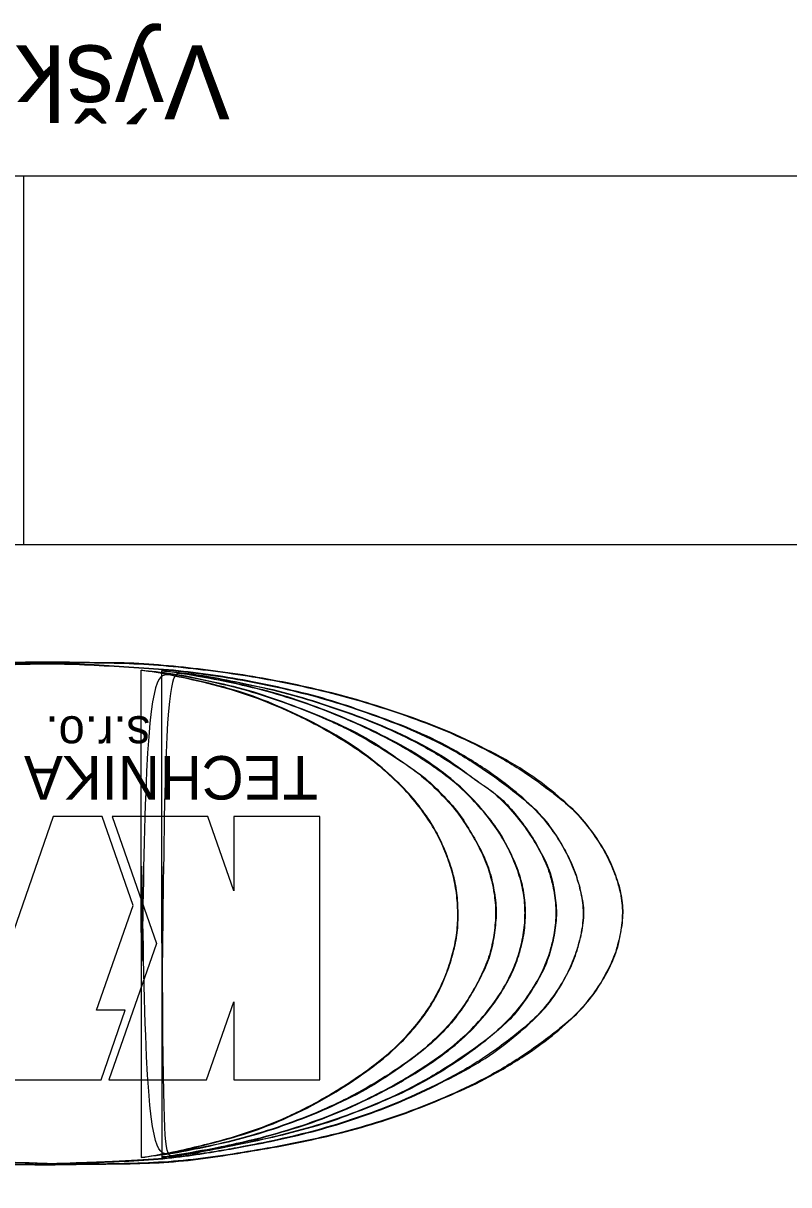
# Model space of a CAD drawing. Extents: x -728472.2 to -728419.7, y -1073099.3 to -1073025.
# Drawn here: x -728457.28 to -728452.08, y -1073054.87 to -1073046.99 of the extents above; entities that cross this region are included whole.
import ezdxf

# ---------------------------------------------------------------- set-up
doc = ezdxf.new("R2010")
doc.units = 0
doc.layers.add('_popis', color=7, linetype='Continuous')
doc.layers.add('Rozpiska_pole_6', color=7, linetype='Continuous')

msp = doc.modelspace()

# ---------------------------------------------------------------- linework, layer by layer
at = {"layer": '_popis'}
for points in [[(-728456.7476, -1073054.1561), (-728456.5834, -1073053.6842), (-728456.7772, -1073053.6842), (-728456.5302, -1073052.9747), (-728456.7404, -1073052.3709), (-728457.0726, -1073052.3709), (-728457.5297, -1073053.6842), (-728457.6809, -1073053.6842), (-728457.8451, -1073054.1561), (-728456.7476, -1073054.1561)], [(-728456.7476, -1073054.1561), (-728456.5834, -1073053.6842), (-728456.7772, -1073053.6842), (-728456.5302, -1073052.9747), (-728456.7404, -1073052.3709), (-728457.0726, -1073052.3709), (-728457.5297, -1073053.6842), (-728457.6809, -1073053.6842), (-728457.8451, -1073054.1561), (-728456.7476, -1073054.1561)], [(-728455.2632, -1073054.1561), (-728455.2632, -1073052.3709), (-728455.8474, -1073052.3709), (-728455.8474, -1073052.874), (-728456.0225, -1073052.3709), (-728456.6724, -1073052.3709), (-728456.3725, -1073053.2324), (-728456.694, -1073054.1561), (-728456.0316, -1073054.1561), (-728455.8474, -1073053.6268), (-728455.8474, -1073054.1561), (-728455.2632, -1073054.1561)], [(-728455.2632, -1073054.1561), (-728455.2632, -1073052.3709), (-728455.8474, -1073052.3709), (-728455.8474, -1073052.874), (-728456.0225, -1073052.3709), (-728456.6724, -1073052.3709), (-728456.3725, -1073053.2324), (-728456.694, -1073054.1561), (-728456.0316, -1073054.1561), (-728455.8474, -1073053.6268), (-728455.8474, -1073054.1561), (-728455.2632, -1073054.1561)]]:
    msp.add_lwpolyline(points, dxfattribs=at)
for points in [[(-728457.7091, -1073051.3386), (-728457.7726, -1073051.3422), (-728457.925, -1073051.3531), (-728458.1678, -1073051.3735), (-728458.4349, -1073051.4173), (-728458.7039, -1073051.4628), (-728458.9726, -1073051.5237), (-728459.2412, -1073051.5978), (-728459.5099, -1073051.6866), (-728459.779, -1073051.7895), (-728460.0492, -1073051.9158), (-728460.3251, -1073052.0723), (-728460.5215, -1073052.2333), (-728460.6799, -1073052.366), (-728460.7644, -1073052.4858), (-728460.8578, -1073052.6154), (-728460.9179, -1073052.7534), (-728460.9631, -1073052.8875), (-728460.989, -1073053.0235), (-728460.9707, -1073053.1621), (-728460.9194, -1073053.2951), (-728460.8626, -1073053.4322), (-728460.7785, -1073053.5688), (-728460.681, -1073053.6813), (-728460.5301, -1073053.8296), (-728460.3243, -1073053.9851), (-728460.0511, -1073054.1448), (-728459.7818, -1073054.2742), (-728459.5101, -1073054.3742), (-728459.2438, -1073054.4708), (-728458.9726, -1073054.5378), (-728458.7045, -1073054.6), (-728458.434, -1073054.6453), (-728458.1654, -1073054.6802), (-728457.8989, -1073054.7218), (-728457.6308, -1073054.7247), (-728457.363, -1073054.7305), (-728457.1843, -1073054.7318), (-728457.0948, -1073054.7325)], [(-728457.0948, -1073054.7325), (-728456.7918, -1073054.7282), (-728456.5586, -1073054.7252), (-728456.2906, -1073054.7141), (-728456.0227, -1073054.6861), (-728455.7547, -1073054.644), (-728455.4862, -1073054.5975), (-728455.2182, -1073054.54), (-728454.9503, -1073054.4699), (-728454.6816, -1073054.3822), (-728454.4137, -1073054.2757), (-728454.1472, -1073054.1523), (-728453.8786, -1073053.9935), (-728453.6107, -1073053.7917), (-728453.5065, -1073053.6944), (-728453.3971, -1073053.5598), (-728453.3157, -1073053.4266), (-728453.2554, -1073053.292), (-728453.2231, -1073053.1586), (-728453.2078, -1073053.0243), (-728453.2217, -1073052.8922), (-728453.2624, -1073052.7568), (-728453.3227, -1073052.6222), (-728453.4069, -1073052.489), (-728453.5149, -1073052.3544), (-728453.6106, -1073052.265), (-728453.8785, -1073052.0617), (-728454.1464, -1073051.9103), (-728454.4116, -1073051.787), (-728454.6823, -1073051.6846), (-728454.9512, -1073051.5973), (-728455.2178, -1073051.5244), (-728455.4843, -1073051.4655), (-728455.7536, -1073051.4164), (-728456.0224, -1073051.3784), (-728456.2917, -1073051.349), (-728456.5568, -1073051.3307), (-728456.8269, -1073051.3278), (-728457.0948, -1073051.3234), (-728457.3627, -1073051.3278), (-728457.6315, -1073051.3348), (-728457.8994, -1073051.3516), (-728458.166, -1073051.3768), (-728458.4347, -1073051.4175), (-728458.7027, -1073051.4652), (-728458.9706, -1073051.5254), (-728459.2396, -1073051.5998), (-728459.5075, -1073051.6881), (-728459.7754, -1073051.7918), (-728460.042, -1073051.9166), (-728460.312, -1073052.0746), (-728460.5813, -1073052.2835), (-728460.6613, -1073052.355), (-728460.7665, -1073052.4882), (-728460.8549, -1073052.6214), (-728460.917, -1073052.7567), (-728460.9605, -1073052.8899), (-728460.9818, -1073053.0243), (-728460.9661, -1073053.158), (-728460.9198, -1073053.2926), (-728460.8594, -1073053.4295), (-728460.7795, -1073053.5599), (-728460.6659, -1073053.6944), (-728460.5831, -1073053.7758), (-728460.3122, -1073053.9854), (-728460.0443, -1073054.1438), (-728459.7781, -1073054.2707), (-728459.5088, -1073054.3745), (-728459.2395, -1073054.467), (-728458.9729, -1073054.5371), (-728458.7028, -1073054.5974), (-728458.4334, -1073054.6437), (-728458.1641, -1073054.6816), (-728457.8983, -1073054.7154), (-728457.6309, -1073054.7252), (-728457.3633, -1073054.7299), (-728457.0948, -1073054.7325), (-728457.0948, -1073054.7325), (-728457.0948, -1073054.7325)], [(-728457.0948, -1073054.7252), (-728457.1843, -1073054.7215), (-728457.3632, -1073054.7142), (-728457.6318, -1073054.7117), (-728457.8994, -1073054.6823), (-728458.1675, -1073054.6482), (-728458.4362, -1073054.6035), (-728458.704, -1073054.5443), (-728458.9744, -1073054.4802), (-728459.2417, -1073054.389), (-728459.5122, -1073054.2858), (-728459.7795, -1073054.1537), (-728460.0582, -1073054.0039), (-728460.2639, -1073053.84), (-728460.4163, -1073053.6872), (-728460.5124, -1073053.566), (-728460.5949, -1073053.4304), (-728460.6561, -1073053.296), (-728460.6882, -1073053.1591), (-728460.6999, -1073053.0238), (-728460.6897, -1073052.8873), (-728460.6489, -1073052.7527), (-728460.5887, -1073052.6175), (-728460.5032, -1073052.4835), (-728460.4121, -1073052.3643), (-728460.2577, -1073052.2194), (-728460.0581, -1073052.0546), (-728459.7814, -1073051.8986), (-728459.511, -1073051.7735), (-728459.242, -1073051.669), (-728458.9724, -1073051.5847), (-728458.7045, -1073051.51), (-728458.4353, -1073051.4543), (-728458.1674, -1073051.4053), (-728457.8986, -1073051.379), (-728457.6309, -1073051.356), (-728457.3632, -1073051.3388), (-728457.0947, -1073051.3301), (-728456.8264, -1073051.3401), (-728456.5586, -1073051.3592), (-728456.2898, -1073051.3739), (-728456.0214, -1073051.4058), (-728455.7529, -1073051.4493), (-728455.4847, -1073051.5062), (-728455.2148, -1073051.5726), (-728454.9483, -1073051.6648), (-728454.6772, -1073051.7619), (-728454.4059, -1073051.8851), (-728454.1363, -1073052.0484), (-728453.9248, -1073052.2091), (-728453.7633, -1073052.3565), (-728453.6669, -1073052.4825), (-728453.5871, -1073052.6187), (-728453.5268, -1073052.7533), (-728453.4896, -1073052.8885), (-728453.4658, -1073053.0241), (-728453.4866, -1073053.1601), (-728453.5212, -1073053.2956), (-728453.578, -1073053.4308), (-728453.6574, -1073053.5657), (-728453.754, -1073053.6974), (-728453.9216, -1073053.8464), (-728454.1329, -1073054.0145), (-728454.4102, -1073054.1627), (-728454.6774, -1073054.2922), (-728454.947, -1073054.3972), (-728455.2159, -1073054.4831), (-728455.4849, -1073054.5519), (-728455.714, -1073054.5973), (-728455.8931, -1073054.6301), (-728456.0715, -1073054.6588), (-728456.2898, -1073054.6909), (-728456.5585, -1073054.7078), (-728456.8266, -1073054.7189), (-728457.0054, -1073054.7231), (-728457.0948, -1073054.7252)], [(-728457.0948, -1073054.7252), (-728456.8266, -1073054.7181), (-728456.5587, -1073054.7069), (-728456.2908, -1073054.6872), (-728456.0228, -1073054.6508), (-728455.9022, -1073054.6312), (-728455.7549, -1073054.6045), (-728455.4863, -1073054.5496), (-728455.2183, -1073054.4809), (-728454.9498, -1073054.3951), (-728454.6819, -1073054.2899), (-728454.4136, -1073054.1622), (-728454.1471, -1073054.0122), (-728453.8788, -1073053.8071), (-728453.7594, -1073053.6946), (-728453.657, -1073053.5601), (-728453.5798, -1073053.4269), (-728453.5237, -1073053.2919), (-728453.4886, -1073053.1587), (-728453.4732, -1073053.0241), (-728453.4914, -1073052.8903), (-728453.5293, -1073052.7571), (-728453.5882, -1073052.6225), (-728453.6669, -1073052.4885), (-728453.7721, -1073052.3539), (-728453.8787, -1073052.253), (-728454.1467, -1073052.0483), (-728454.4136, -1073051.8879), (-728454.6815, -1073051.7645), (-728454.9494, -1073051.665), (-728455.218, -1073051.5761), (-728455.4859, -1073051.5074), (-728455.7539, -1073051.4514), (-728456.0225, -1073051.4076), (-728456.2904, -1073051.3767), (-728456.5584, -1073051.3585), (-728456.8268, -1073051.3416), (-728457.0948, -1073051.3332), (-728457.3627, -1073051.3402), (-728457.6314, -1073051.357), (-728457.8979, -1073051.3795), (-728458.1659, -1073051.4089), (-728458.4346, -1073051.4553), (-728458.7025, -1073051.5127), (-728458.9705, -1073051.5856), (-728459.2393, -1073051.6715), (-728459.5073, -1073051.7752), (-728459.7752, -1073051.9), (-728460.0437, -1073052.0565), (-728460.3117, -1073052.271), (-728460.3975, -1073052.3543), (-728460.5041, -1073052.4889), (-728460.5869, -1073052.6221), (-728460.6472, -1073052.7566), (-728460.685, -1073052.8898), (-728460.6963, -1073053.023), (-728460.685, -1073053.1581), (-728460.6528, -1073053.2913), (-728460.5939, -1073053.4259), (-728460.5124, -1073053.56), (-728460.4058, -1073053.6946), (-728460.3118, -1073053.7899), (-728460.0439, -1073054.0016), (-728459.7754, -1073054.1539), (-728459.5075, -1073054.2828), (-728459.2395, -1073054.388), (-728458.9711, -1073054.4765), (-728458.7031, -1073054.5438), (-728458.4352, -1073054.6013), (-728458.1666, -1073054.6466), (-728457.8986, -1073054.6816), (-728457.6314, -1073054.7072), (-728457.3635, -1073054.7156), (-728457.0948, -1073054.7252), (-728457.0948, -1073054.7252), (-728457.0948, -1073054.7252)], [(-728457.0948, -1073054.7325), (-728456.9938, -1073054.7309), (-728456.8151, -1073054.7281), (-728456.547, -1073054.7261), (-728456.29, -1073054.7173), (-728456.0217, -1073054.6887), (-728455.7543, -1073054.6438), (-728455.4853, -1073054.5997), (-728455.2169, -1073054.5415), (-728454.9477, -1073054.4722), (-728454.6787, -1073054.3847), (-728454.4114, -1073054.2766), (-728454.1391, -1073054.1548), (-728453.869, -1073053.9939), (-728453.6575, -1073053.836), (-728453.4965, -1073053.6898), (-728453.3973, -1073053.5665), (-728453.315, -1073053.4304), (-728453.2512, -1073053.297), (-728453.2219, -1073053.1596), (-728453.2018, -1073053.0253), (-728453.2182, -1073052.8883), (-728453.2607, -1073052.754), (-728453.3206, -1073052.6172), (-728453.4081, -1073052.4838), (-728453.5021, -1073052.3613), (-728453.661, -1073052.2185), (-728453.8658, -1073052.0597), (-728454.1406, -1073051.91), (-728454.409, -1073051.7834), (-728454.6797, -1073051.6836), (-728454.9485, -1073051.5958), (-728455.2161, -1073051.5222), (-728455.4843, -1073051.4641), (-728455.7525, -1073051.4146), (-728456.0221, -1073051.3771), (-728456.2898, -1073051.3478), (-728456.5581, -1073051.3266), (-728456.8262, -1073051.33), (-728457.0948, -1073051.3205), (-728457.363, -1073051.3286), (-728457.5679, -1073051.3314), (-728457.6832, -1073051.3371), (-728457.7091, -1073051.3386)], [(-728456.4751, -1073051.3789), (-728456.4136, -1073051.3842), (-728456.2609, -1073051.3973), (-728456.0217, -1073051.4486), (-728455.7512, -1073051.5094), (-728455.4844, -1073051.6019), (-728455.2139, -1073051.7058), (-728454.9396, -1073051.8358), (-728454.7376, -1073051.979), (-728454.5582, -1073052.0973), (-728454.4396, -1073052.2148), (-728454.3179, -1073052.3459), (-728454.2351, -1073052.4868), (-728454.1582, -1073052.6179), (-728454.1065, -1073052.7528), (-728454.078, -1073052.8881), (-728454.0631, -1073053.0237), (-728454.0794, -1073053.1589), (-728454.1004, -1073053.2957), (-728454.1559, -1073053.4298), (-728454.2276, -1073053.5634), (-728454.3146, -1073053.7009), (-728454.428, -1073053.838), (-728454.5561, -1073053.952), (-728454.7306, -1073054.0837), (-728454.9416, -1073054.2219), (-728455.2133, -1073054.3551), (-728455.4828, -1073054.46), (-728455.7507, -1073054.5482), (-728456.0206, -1073054.6094), (-728456.2611, -1073054.6592), (-728456.4137, -1073054.6766), (-728456.4752, -1073054.6836)], [(-728456.4752, -1073054.6836), (-728456.4136, -1073054.6747), (-728456.2614, -1073054.6526), (-728456.0213, -1073054.5933), (-728455.7501, -1073054.5212), (-728455.4798, -1073054.4158), (-728455.2102, -1073054.277), (-728454.9739, -1073054.1226), (-728454.7805, -1073053.9738), (-728454.6453, -1073053.8341), (-728454.5388, -1073053.7004), (-728454.458, -1073053.5647), (-728454.3998, -1073053.429), (-728454.3564, -1073053.2942), (-728454.3284, -1073053.1595), (-728454.3244, -1073053.0241), (-728454.3322, -1073052.8892), (-728454.3583, -1073052.7536), (-728454.4061, -1073052.6202), (-728454.4651, -1073052.4836), (-728454.5499, -1073052.3502), (-728454.6565, -1073052.2144), (-728454.7915, -1073052.0814), (-728454.9755, -1073051.9282), (-728455.21, -1073051.7818), (-728455.4807, -1073051.6481), (-728455.7495, -1073051.5384), (-728456.0205, -1073051.4632), (-728456.2624, -1073051.413), (-728456.4136, -1073051.3888), (-728456.4751, -1073051.3789)], [(-728456.4751, -1073051.3789), (-728456.2909, -1073051.3979), (-728456.0215, -1073051.4491), (-728455.756, -1073051.5134), (-728455.4866, -1073051.6028), (-728455.2178, -1073051.7082), (-728454.951, -1073051.8395), (-728454.6823, -1073052.015), (-728454.5811, -1073052.0859), (-728454.4352, -1073052.2212), (-728454.3196, -1073052.3539), (-728454.2341, -1073052.4886), (-728454.1605, -1073052.6226), (-728454.1092, -1073052.7566), (-728454.0803, -1073052.888), (-728454.0683, -1073053.0238), (-728454.0801, -1073053.1591), (-728454.1051, -1073053.2918), (-728454.1564, -1073053.425), (-728454.2287, -1073053.5616), (-728454.3141, -1073053.6942), (-728454.4259, -1073053.8289), (-728454.5731, -1073053.9629), (-728454.6835, -1073054.047), (-728454.9506, -1073054.2197), (-728455.2174, -1073054.3523), (-728455.4869, -1073054.4587), (-728455.753, -1073054.5443), (-728456.0212, -1073054.6086), (-728456.291, -1073054.6603), (-728456.4752, -1073054.6836), (-728456.4751, -1073051.3789), (-728456.4752, -1073054.6836)], [(-728456.4752, -1073054.6836), (-728456.2909, -1073054.6544), (-728456.0232, -1073054.593), (-728455.754, -1073054.5169), (-728455.4863, -1073054.4131), (-728455.218, -1073054.2753), (-728454.9502, -1073054.1013), (-728454.7743, -1073053.9614), (-728454.6441, -1073053.8284), (-728454.5387, -1073053.6939), (-728454.4597, -1073053.5608), (-728454.4012, -1073053.4263), (-728454.3585, -1073053.2923), (-728454.3322, -1073053.1578), (-728454.3263, -1073053.0248), (-728454.3351, -1073052.8903), (-728454.3614, -1073052.7558), (-728454.4068, -1073052.6227), (-728454.4669, -1073052.4888), (-728454.5503, -1073052.3543), (-728454.6542, -1073052.2227), (-728454.7889, -1073052.0875), (-728454.9499, -1073051.9545), (-728455.2176, -1073051.7834), (-728455.4857, -1073051.6497), (-728455.7534, -1073051.5429), (-728456.0241, -1073051.4654), (-728456.2908, -1073051.4096), (-728456.4751, -1073051.3789), (-728456.4752, -1073054.6836), (-728456.4751, -1073051.3789)], [(-728456.3344, -1073054.68), (-728456.2378, -1073054.6656), (-728456.0435, -1073054.6364), (-728455.7596, -1073054.5781), (-728455.4831, -1073054.5019), (-728455.2129, -1073054.4126), (-728454.9452, -1073054.2943), (-728454.6747, -1073054.1526), (-728454.4376, -1073053.9979), (-728454.2516, -1073053.8423), (-728454.1278, -1073053.6997), (-728454.0305, -1073053.5665), (-728453.9583, -1073053.4311), (-728453.9064, -1073053.2955), (-728453.8755, -1073053.1594), (-728453.8664, -1073053.0235), (-728453.8762, -1073052.8884), (-728453.9102, -1073052.7528), (-728453.9678, -1073052.6195), (-728454.0383, -1073052.4818), (-728454.1394, -1073052.3496), (-728454.2618, -1073052.2104), (-728454.4413, -1073052.0553), (-728454.6746, -1073051.9033), (-728454.9465, -1073051.7666), (-728455.2159, -1073051.6521), (-728455.4834, -1073051.5565), (-728455.7526, -1073051.4846), (-728455.9957, -1073051.4352), (-728456.1901, -1073051.4028), (-728456.2947, -1073051.3886), (-728456.3354, -1073051.3831)], [(-728456.3354, -1073051.3831), (-728456.2841, -1073051.3873), (-728456.1789, -1073051.396), (-728455.9845, -1073051.4257), (-728455.7521, -1073051.4736), (-728455.4811, -1073051.5313), (-728455.214, -1073051.6169), (-728454.9445, -1073051.7097), (-728454.6747, -1073051.8264), (-728454.401, -1073051.9731), (-728454.2107, -1073052.1233), (-728454.0413, -1073052.235), (-728453.9409, -1073052.3479), (-728453.8386, -1073052.4843), (-728453.7593, -1073052.6188), (-728453.6974, -1073052.7516), (-728453.6702, -1073052.8892), (-728453.6552, -1073053.0241), (-728453.6697, -1073053.1597), (-728453.7007, -1073053.2953), (-728453.7529, -1073053.4331), (-728453.8362, -1073053.5638), (-728453.932, -1073053.7058), (-728454.0417, -1073053.8112), (-728454.2019, -1073053.9417), (-728454.4035, -1073054.0831), (-728454.6751, -1073054.2361), (-728454.9468, -1073054.3499), (-728455.2141, -1073054.4518), (-728455.4843, -1073054.5243), (-728455.7548, -1073054.5852), (-728456.0223, -1073054.6384), (-728456.216, -1073054.6729), (-728456.3204, -1073054.6792), (-728456.3344, -1073054.68)], [(-728456.3354, -1073051.3831), (-728456.1817, -1073051.3975), (-728456.0213, -1073051.4211), (-728455.7532, -1073051.4737), (-728455.4838, -1073051.5354), (-728455.215, -1073051.6176), (-728454.9482, -1073051.7122), (-728454.6814, -1073051.8278), (-728454.4125, -1073051.9768), (-728454.143, -1073052.1673), (-728454.0707, -1073052.2185), (-728453.9393, -1073052.3538), (-728453.8377, -1073052.491), (-728453.7602, -1073052.6224), (-728453.7023, -1073052.755), (-728453.6719, -1073052.891), (-728453.66, -1073053.025), (-728453.6719, -1073053.1564), (-728453.7034, -1073053.293), (-728453.756, -1073053.4279), (-728453.8349, -1073053.5605), (-728453.9308, -1073053.6945), (-728454.0675, -1073053.8311), (-728454.1411, -1073053.8915), (-728454.4125, -1073054.0825), (-728454.6832, -1073054.2336), (-728454.9504, -1073054.3497), (-728455.2146, -1073054.4469), (-728455.4887, -1073054.5235), (-728455.7542, -1073054.5839), (-728456.0236, -1073054.6377), (-728456.2924, -1073054.6773), (-728456.3344, -1073054.68), (-728456.3354, -1073051.3831), (-728456.3344, -1073054.68)], [(-728456.3344, -1073054.68), (-728456.0452, -1073054.634), (-728455.7547, -1073054.5736), (-728455.4853, -1073054.5001), (-728455.2163, -1073054.409), (-728454.9508, -1073054.2934), (-728454.6826, -1073054.1515), (-728454.4138, -1073053.9734), (-728454.2456, -1073053.8289), (-728454.126, -1073053.6936), (-728454.0314, -1073053.5609), (-728453.9604, -1073053.4283), (-728453.909, -1073053.2923), (-728453.8787, -1073053.157), (-728453.8695, -1073053.0243), (-728453.88, -1073052.8894), (-728453.9129, -1073052.7567), (-728453.9681, -1073052.6227), (-728454.0404, -1073052.4874), (-728454.1377, -1073052.3548), (-728454.2575, -1073052.221), (-728454.4165, -1073052.0818), (-728454.682, -1073051.9058), (-728454.9514, -1073051.7678), (-728455.219, -1073051.6539), (-728455.4871, -1073051.5594), (-728455.7539, -1073051.4871), (-728456.0226, -1073051.4317), (-728456.2132, -1073051.4001), (-728456.3354, -1073051.3831), (-728456.3344, -1073054.68), (-728456.3354, -1073051.3831)]]:
    msp.add_open_spline(points, degree=3, dxfattribs=at)
at = {"layer": 'Rozpiska_pole_6'}
for p, q in [((-728457.2725, -1073048.028), (-728457.2725, -1073050.528)), ((-728424.685, -1073050.528), (-728467.185, -1073050.528))]:
    msp.add_line(p, q, dxfattribs=at)
msp.add_lwpolyline([(-728424.685, -1073060.528), (-728467.185, -1073060.528), (-728467.185, -1073048.028), (-728424.685, -1073048.028)], close=True, dxfattribs=at)

# ---------------------------------------------------------------- texts
at = {"layer": '_popis'}
for s, height, p in [('s.r.o.', 0.23858, (-728456.4147, -1073051.6913)), ('TECHNIKA', 0.29488, (-728455.2756, -1073051.9609))]:
    msp.add_text(s, height=height, rotation=180, dxfattribs=at).set_placement(p)
at = {"layer": 'Rozpiska_pole_6'}
msp.add_text('Výškový systém : BpV', height=0.5, rotation=180, dxfattribs=at).set_placement((-728455.8741, -1073047.1432))

doc.saveas('drawing.dxf')
